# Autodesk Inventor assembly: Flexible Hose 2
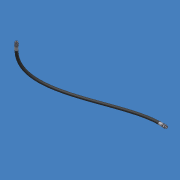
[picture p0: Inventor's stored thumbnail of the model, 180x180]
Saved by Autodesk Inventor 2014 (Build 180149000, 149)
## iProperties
TPVersion: 11.0.2
Company: Autodesk, Inc.
Name: Hydraulic Hose - Male Straight Thread
ActiveState: True
PipeType: Flexible Hose
Material: UnInitValue
Standard: UnInitValue
FittingMaterial: UnInitValue
FittingStandard: UnInitValue
RouteDirection90: UnInitValue
RouteDirection45: UnInitValue
DiameterType: Nominal
Diameter: 1/2
Schedule: ID=0.5
OD: 0.880 in
ID: 0.500 in
Ending: UnInitValue
RoundUpValue: 0.125 in
DefaultBendRadius: UnInitValue
BendRadius: 0.500 in
PipingComponentColor: As Material
PipeKey: v3#d489867e-ac9b-47ea-b952-0a1b885f66be#4
CouplingKey: UnInitValue
StartFittingKey: v3#b50cb43e-68c0-48ac-8e25-7ef224ce0e6c#3
EndFittingKey: v3#b50cb43e-68c0-48ac-8e25-7ef224ce0e6c#3
Elbow90Key: UnInitValue
Elbow45Key: UnInitValue
SuppressStartFitting: False
SuppressEndFitting: False
UseSubASM: True
_ComponentInfo: <CS><C N="Pipe" R="1.117600" OR="1.117600" IR="0.635000" PL="PL" PartType="pipe" SymKey="" PN="Parker Hydraulic Hose - No Skive 1/2"><CO N="1"><FE V="0"/><FD V=
FlangeKey: UnInitValue
Gap: UnInitValue
GasketKey: UnInitValue
IsButtWelded: UnInitValue
IsFlanged: UnInitValue
MixedUnits: UnInitValue
ShowGap: UnInitValue
UseFlangsForCouplings: UnInitValue
Angle: UnInitValue
ElbowCustomKey: UnInitValue
IsSelfDraining: UnInitValue
Created: 2005-03
Part Number: Flexible Hose 2
Document SubType Name: Tube & Pipe
Designer: Autodesk, Inc.
Mass: 507.426 g
Surface Area: 1513.46 cm^2
Volume: 335.879 cm^3
Density: 1.51074 g/cm^3
Author: Autodesk, Inc.
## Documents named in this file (4)
- C:\Users\iTools\Desktop\tutorial files\Tube and Pipe\Accumulator\AIP\Hose Run1\pifhose.1110965117912.iam
- C:\Users\iTools\Desktop\tutorial files\Tube and Pipe\Accumulator\AIP\Hose Run1\piroute.1110965118600.ipt
- C:\Users\iTools\Desktop\tutorial files\Tube and Pipe\Accumulator\Standard Parts\Parker Male Straight Thread 1_2 x 3_4-16 UNF.ipt
- C:\Users\iTools\Desktop\tutorial files\Tube and Pipe\Accumulator\AIP\Hose Run1\pifhose.1202152271534.ipt
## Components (4 placed, 3 different names)
1. Pipe Route 2
2. Parker Male Straight Thread 1/2 x 3/4-16 UNF:1
3. Parker Male Straight Thread 1/2 x 3/4-16 UNF:2
4. Flexible Hose:3
